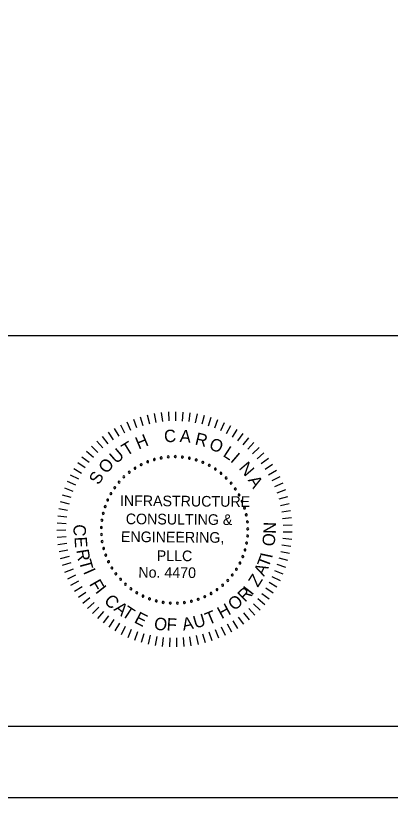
# Model space of a CAD drawing. Extents: x -121.2 to -24.9, y 6.4 to 65.
# Drawn here: x -53.92 to -46.89, y 6.35 to 21.02 of the extents above; entities that cross this region are included whole.
import ezdxf

# ---------------------------------------------------------------- set-up
doc = ezdxf.new("R2010")
doc.units = 0
for name, color, linetype in [('BR_BORDER LINES', 7, 'Continuous'), ('BR_TEXT', 7, 'Continuous'), ('Level 31', 7, 'Continuous')]:
    doc.layers.add(name, color=color, linetype=linetype)

msp = doc.modelspace()

# ---------------------------------------------------------------- linework, layer by layer
at = {"layer": 'BR_BORDER LINES'}
for p, q in [((-60.804, 15.017), (-46.496, 15.017)), ((-116.272, 7.683), (-26.496, 7.683))]:
    msp.add_line(p, q, dxfattribs=at)
at = {"layer": 'BR_TEXT'}
for p, q in [((-51.453, 13.526), (-51.413, 13.36)), ((-51.321, 13.553), (-51.292, 13.386)), ((-51.188, 13.572), (-51.169, 13.403)), ((-51.054, 13.583), (-51.045, 13.413)), ((-50.919, 13.586), (-50.921, 13.416)), ((-50.785, 13.58), (-50.796, 13.411)), ((-50.651, 13.567), (-50.673, 13.399)), ((-50.518, 13.545), (-50.55, 13.378)), ((-50.387, 13.515), (-50.429, 13.351)), ((-51.835, 13.396), (-51.766, 13.241)), ((-51.711, 13.447), (-51.651, 13.288)), ((-51.583, 13.49), (-51.533, 13.328)), ((-50.257, 13.478), (-50.31, 13.316)), ((-50.131, 13.432), (-50.193, 13.274)), ((-50.007, 13.379), (-50.079, 13.225)), ((-52.074, 13.272), (-51.987, 13.127)), ((-51.957, 13.338), (-51.878, 13.187)), ((-49.887, 13.318), (-49.968, 13.169)), ((-49.771, 13.251), (-49.86, 13.106)), ((-52.296, 13.12), (-52.192, 12.986)), ((-52.187, 13.2), (-52.091, 13.06)), ((-49.659, 13.176), (-49.757, 13.037)), ((-49.551, 13.094), (-49.658, 12.962)), ((-52.498, 12.942), (-52.378, 12.822)), ((-52.4, 13.034), (-52.287, 12.907)), ((-49.449, 13.006), (-49.564, 12.881)), ((-49.353, 12.913), (-49.475, 12.794)), ((-52.59, 12.844), (-52.463, 12.732)), ((-49.262, 12.813), (-49.391, 12.702)), ((-52.757, 12.633), (-52.617, 12.536)), ((-52.677, 12.741), (-52.543, 12.636)), ((-49.178, 12.708), (-49.313, 12.606)), ((-52.83, 12.52), (-52.684, 12.432)), ((-49.1, 12.598), (-49.242, 12.504)), ((-49.029, 12.484), (-49.176, 12.398)), ((-52.896, 12.402), (-52.745, 12.324)), ((-48.966, 12.365), (-49.117, 12.289)), ((-52.954, 12.281), (-52.799, 12.212)), ((-48.909, 12.243), (-49.065, 12.176)), ((-53.049, 12.029), (-52.887, 11.98)), ((-53.006, 12.157), (-52.847, 12.097)), ((-48.86, 12.117), (-49.02, 12.06)), ((-53.085, 11.9), (-52.92, 11.86)), ((-48.819, 11.989), (-48.982, 11.942)), ((-53.113, 11.768), (-52.946, 11.738)), ((-48.786, 11.859), (-48.951, 11.822)), ((-53.132, 11.635), (-52.964, 11.615)), ((-48.761, 11.727), (-48.928, 11.7)), ((-48.743, 11.593), (-48.912, 11.576)), ((-53.144, 11.501), (-52.974, 11.491)), ((-48.734, 11.459), (-48.904, 11.452)), ((-53.147, 11.366), (-52.978, 11.367)), ((-48.734, 11.324), (-48.903, 11.328)), ((-53.142, 11.231), (-52.973, 11.243)), ((-48.741, 11.19), (-48.91, 11.204)), ((-53.129, 11.097), (-52.961, 11.119)), ((-48.757, 11.056), (-48.925, 11.081)), ((-53.108, 10.965), (-52.941, 10.997)), ((-53.079, 10.833), (-52.914, 10.875)), ((-48.78, 10.923), (-48.947, 10.958)), ((-53.042, 10.704), (-52.88, 10.756)), ((-48.852, 10.664), (-49.013, 10.719)), ((-48.812, 10.793), (-48.976, 10.838)), ((-52.997, 10.577), (-52.838, 10.639)), ((-48.899, 10.538), (-49.056, 10.603)), ((-52.944, 10.453), (-52.79, 10.524)), ((-48.954, 10.415), (-49.107, 10.489)), ((-52.884, 10.333), (-52.734, 10.413)), ((-52.816, 10.216), (-52.672, 10.306)), ((-49.086, 10.181), (-49.229, 10.273)), ((-49.017, 10.296), (-49.165, 10.379)), ((-52.742, 10.104), (-52.603, 10.202)), ((-49.163, 10.07), (-49.3, 10.17)), ((-52.661, 9.996), (-52.529, 10.103)), ((-52.573, 9.894), (-52.448, 10.008)), ((-49.335, 9.863), (-49.459, 9.98)), ((-49.246, 9.964), (-49.376, 10.073)), ((-52.48, 9.797), (-52.362, 9.919)), ((-52.381, 9.706), (-52.27, 9.835)), ((-49.431, 9.768), (-49.547, 9.892)), ((-52.276, 9.622), (-52.173, 9.757)), ((-52.166, 9.543), (-52.072, 9.685)), ((-49.638, 9.597), (-49.738, 9.734)), ((-49.532, 9.679), (-49.64, 9.81)), ((-52.052, 9.472), (-51.967, 9.619)), ((-51.934, 9.408), (-51.858, 9.56)), ((-49.984, 9.389), (-50.058, 9.542)), ((-49.864, 9.451), (-49.947, 9.6)), ((-49.749, 9.521), (-49.841, 9.663)), ((-51.812, 9.351), (-51.745, 9.507)), ((-51.687, 9.302), (-51.629, 9.461)), ((-51.559, 9.26), (-51.511, 9.423)), ((-51.428, 9.226), (-51.391, 9.392)), ((-50.362, 9.249), (-50.407, 9.412)), ((-50.233, 9.288), (-50.288, 9.449)), ((-50.107, 9.335), (-50.171, 9.492)), ((-51.296, 9.2), (-51.269, 9.368)), ((-51.163, 9.183), (-51.146, 9.352)), ((-51.028, 9.173), (-51.022, 9.343)), ((-50.894, 9.172), (-50.898, 9.342)), ((-50.759, 9.179), (-50.773, 9.348)), ((-50.626, 9.194), (-50.65, 9.362)), ((-50.493, 9.217), (-50.528, 9.384))]:
    msp.add_line(p, q, dxfattribs=at)
for centre, start, end in [((-50.926, 12.743), 359.5268, 179.5268), ((-51.445, 12.647), 21.6807, 201.6807), ((-51.445, 12.647), 201.6807, 21.6807), ((-51.319, 12.689), 16.1422, 196.1422), ((-51.319, 12.689), 196.1422, 16.1422), ((-51.19, 12.72), 10.6038, 190.6038), ((-51.19, 12.72), 190.6038, 10.6038), ((-51.058, 12.738), 5.0653, 185.0653), ((-51.058, 12.738), 185.0653, 5.0653), ((-50.926, 12.743), 179.5268, 359.5268), ((-50.793, 12.735), 353.9884, 173.9884), ((-50.793, 12.735), 173.9884, 353.9884), ((-50.662, 12.714), 348.4499, 168.4499), ((-50.662, 12.714), 168.4499, 348.4499), ((-50.533, 12.681), 162.9114, 342.9114), ((-50.533, 12.681), 342.9114, 162.9114), ((-50.408, 12.636), 157.373, 337.373), ((-50.408, 12.636), 337.373, 157.373), ((-51.79, 12.449), 38.2961, 218.2961), ((-51.682, 12.526), 32.7576, 212.7576), ((-51.682, 12.526), 212.7576, 32.7576), ((-51.566, 12.592), 27.2191, 207.2191), ((-51.566, 12.592), 207.2191, 27.2191), ((-50.288, 12.579), 151.8345, 331.8345), ((-50.288, 12.579), 331.8345, 151.8345), ((-50.174, 12.51), 146.2961, 326.2961), ((-50.174, 12.51), 326.2961, 146.2961), ((-51.89, 12.362), 43.8345, 223.8345), ((-51.89, 12.362), 223.8345, 43.8345), ((-51.79, 12.449), 218.2961, 38.2961), ((-50.068, 12.431), 140.7576, 320.7576), ((-50.068, 12.431), 320.7576, 140.7576), ((-49.969, 12.342), 135.2191, 315.2191), ((-49.969, 12.342), 315.2191, 135.2191), ((-52.063, 12.16), 54.9114, 234.9114), ((-52.063, 12.16), 234.9114, 54.9114), ((-51.982, 12.265), 49.373, 229.373), ((-51.982, 12.265), 229.373, 49.373), ((-49.88, 12.244), 129.6807, 309.6807), ((-49.88, 12.244), 309.6807, 129.6807), ((-52.135, 12.048), 60.4499, 240.4499), ((-52.135, 12.048), 240.4499, 60.4499), ((-49.8, 12.137), 124.1422, 304.1422), ((-49.8, 12.137), 304.1422, 124.1422), ((-49.731, 12.024), 118.6038, 298.6038), ((-49.731, 12.024), 298.6038, 118.6038), ((-52.195, 11.93), 65.9884, 245.9884), ((-52.195, 11.93), 245.9884, 65.9884), ((-49.673, 11.904), 113.0653, 293.0653), ((-49.673, 11.904), 293.0653, 113.0653), ((-52.243, 11.806), 71.5268, 251.5268), ((-52.243, 11.806), 251.5268, 71.5268), ((-49.628, 11.779), 107.5268, 287.5268), ((-49.628, 11.779), 287.5268, 107.5268), ((-52.279, 11.678), 77.0653, 257.0653), ((-52.279, 11.678), 257.0653, 77.0653), ((-49.594, 11.651), 101.9884, 281.9884), ((-49.594, 11.651), 281.9884, 101.9884), ((-52.303, 11.547), 82.6038, 262.6038), ((-52.303, 11.547), 262.6038, 82.6038), ((-49.573, 11.519), 96.4499, 276.4499), ((-49.573, 11.519), 276.4499, 96.4499), ((-52.314, 11.415), 88.1422, 268.1422), ((-52.312, 11.282), 93.6807, 273.6807), ((-52.314, 11.415), 268.1422, 88.1422), ((-52.312, 11.282), 273.6807, 93.6807), ((-49.565, 11.387), 90.9114, 270.9114), ((-49.565, 11.387), 270.9114, 90.9114), ((-52.298, 11.15), 99.2191, 279.2191), ((-52.298, 11.15), 279.2191, 99.2191), ((-49.569, 11.254), 85.373, 265.373), ((-49.569, 11.254), 265.373, 85.373), ((-52.27, 11.02), 104.7576, 284.7576), ((-52.27, 11.02), 284.7576, 104.7576), ((-49.617, 10.993), 74.2961, 254.2961), ((-49.617, 10.993), 254.2961, 74.2961), ((-49.587, 11.122), 79.8345, 259.8345), ((-49.587, 11.122), 259.8345, 79.8345), ((-52.231, 10.893), 110.2961, 290.2961), ((-52.231, 10.893), 290.2961, 110.2961), ((-49.659, 10.867), 68.7576, 248.7576), ((-49.659, 10.867), 248.7576, 68.7576), ((-52.179, 10.771), 115.8345, 295.8345), ((-52.179, 10.771), 295.8345, 115.8345), ((-49.713, 10.746), 63.2191, 243.2191), ((-49.713, 10.746), 243.2191, 63.2191), ((-52.115, 10.654), 121.373, 301.373), ((-52.115, 10.654), 301.373, 121.373), ((-52.041, 10.544), 306.9114, 126.9114), ((-49.779, 10.63), 57.6807, 237.6807), ((-49.779, 10.63), 237.6807, 57.6807), ((-52.041, 10.544), 126.9114, 306.9114), ((-51.956, 10.441), 132.4499, 312.4499), ((-51.956, 10.441), 312.4499, 132.4499), ((-49.942, 10.421), 46.6038, 226.6038), ((-49.942, 10.421), 226.6038, 46.6038), ((-49.856, 10.522), 52.1422, 232.1422), ((-49.856, 10.522), 232.1422, 52.1422), ((-51.862, 10.348), 137.9884, 317.9884), ((-51.862, 10.348), 317.9884, 137.9884), ((-51.759, 10.263), 143.5268, 323.5268), ((-51.759, 10.263), 323.5268, 143.5268), ((-50.038, 10.329), 41.0653, 221.0653), ((-50.038, 10.329), 221.0653, 41.0653), ((-51.649, 10.189), 149.0653, 329.0653), ((-51.649, 10.189), 329.0653, 149.0653), ((-51.532, 10.126), 154.6038, 334.6038), ((-51.532, 10.126), 334.6038, 154.6038), ((-50.373, 10.115), 24.4499, 204.4499), ((-50.373, 10.115), 204.4499, 24.4499), ((-50.255, 10.175), 29.9884, 209.9884), ((-50.255, 10.175), 209.9884, 29.9884), ((-50.143, 10.247), 35.5268, 215.5268), ((-50.143, 10.247), 215.5268, 35.5268), ((-51.409, 10.075), 160.1422, 340.1422), ((-51.409, 10.075), 340.1422, 160.1422), ((-51.283, 10.036), 345.6807, 165.6807), ((-51.283, 10.036), 165.6807, 345.6807), ((-51.152, 10.009), 351.2191, 171.2191), ((-51.152, 10.009), 171.2191, 351.2191), ((-51.02, 9.995), 356.7576, 176.7576), ((-51.02, 9.995), 176.7576, 356.7576), ((-50.887, 9.993), 2.2961, 182.2961), ((-50.887, 9.993), 182.2961, 2.2961), ((-50.755, 10.005), 7.8345, 187.8345), ((-50.755, 10.005), 187.8345, 7.8345), ((-50.624, 10.029), 13.373, 193.373), ((-50.624, 10.029), 193.373, 13.373), ((-50.497, 10.066), 18.9114, 198.9114), ((-50.497, 10.066), 198.9114, 18.9114)]:
    msp.add_arc(centre, 0.0187, start, end, dxfattribs=at)
at = {"layer": 'Level 31'}
msp.add_lwpolyline([(-121.161, 65.017), (-121.161, 6.35), (-25.161, 6.35), (-25.161, 65.017)], dxfattribs=at)

# ---------------------------------------------------------------- texts
at = {"layer": 'BR_TEXT'}
for s, height, rotation, p in [('C', 0.233, 4.7281, (-51.127, 13.006)), ('A', 0.233, 355.6981, (-50.848, 13.019)), ('H', 0.233, 22.7882, (-51.615, 12.874)), ('R', 0.233, 346.6681, (-50.57, 12.974)), ('O', 0.233, 337.638, (-50.31, 12.894)), ('T', 0.233, 31.8182, (-51.841, 12.747)), ('L', 0.233, 327.108, (-50.046, 12.759)), ('U', 0.233, 40.8482, (-52.036, 12.597)), ('I', 0.233, 319.578, (-49.906, 12.659)), ('O', 0.233, 49.8782, (-52.215, 12.408)), ('N', 0.233, 310.548, (-49.744, 12.523)), ('S', 0.233, 58.9083, (-52.363, 12.199)), ('A', 0.233, 301.5179, (-49.57, 12.303)), ('INFRASTRUCTURE', 0.19939, 359.5268, (-51.966, 11.819)), ('CONSULTING &', 0.19939, 359.5268, (-51.856, 11.476)), ('C', 0.233, 267.025, (-52.829, 11.479)), ('N', 0.233, 89.2085, (-49.039, 11.293)), ('ENGINEERING,', 0.19939, 359.5268, (-51.946, 11.142)), ('E', 0.233, 273.025, (-52.818, 11.235)), ('O', 0.233, 83.2085, (-49.068, 11.05)), ('R', 0.233, 279.025, (-52.784, 10.989)), ('PLLC', 0.1994, 359.5268, (-51.275, 10.786)), ('T', 0.233, 69.3954, (-49.178, 10.645)), ('I', 0.233, 77.9093, (-49.11, 10.825)), ('T', 0.233, 285.025, (-52.737, 10.779)), ('I', 0.233, 293.7713, (-52.658, 10.584)), ('No. 4470', 0.1994, 359.5268, (-51.62, 10.474)), ('A', 0.233, 63.3954, (-49.26, 10.484)), ('F', 0.233, 299.7713, (-52.548, 10.355)), ('Z', 0.233, 57.3954, (-49.377, 10.28)), ('I', 0.233, 308.5268, (-52.436, 10.211)), ('R', 0.233, 44.5268, (-49.619, 10)), ('I', 0.233, 52.3339, (-49.487, 10.127)), ('C', 0.233, 314.5268, (-52.278, 10.024)), ('O', 0.233, 38.5268, (-49.823, 9.841)), ('A', 0.233, 320.5268, (-52.093, 9.868)), ('H', 0.233, 28.5268, (-50.058, 9.691)), ('T', 0.233, 326.5268, (-51.948, 9.765)), ('E', 0.233, 332.5268, (-51.712, 9.638)), ('T', 0.233, 22.5268, (-50.306, 9.58)), ('O', 0.233, 350.5268, (-51.338, 9.508)), ('F', 0.233, 356.5268, (-51.094, 9.483)), ('A', 0.233, 10.5268, (-50.775, 9.479)), ('U', 0.233, 16.5268, (-50.551, 9.515))]:
    msp.add_text(s, height=height, rotation=rotation, dxfattribs=at).set_placement(p)

doc.saveas('drawing.dxf')
